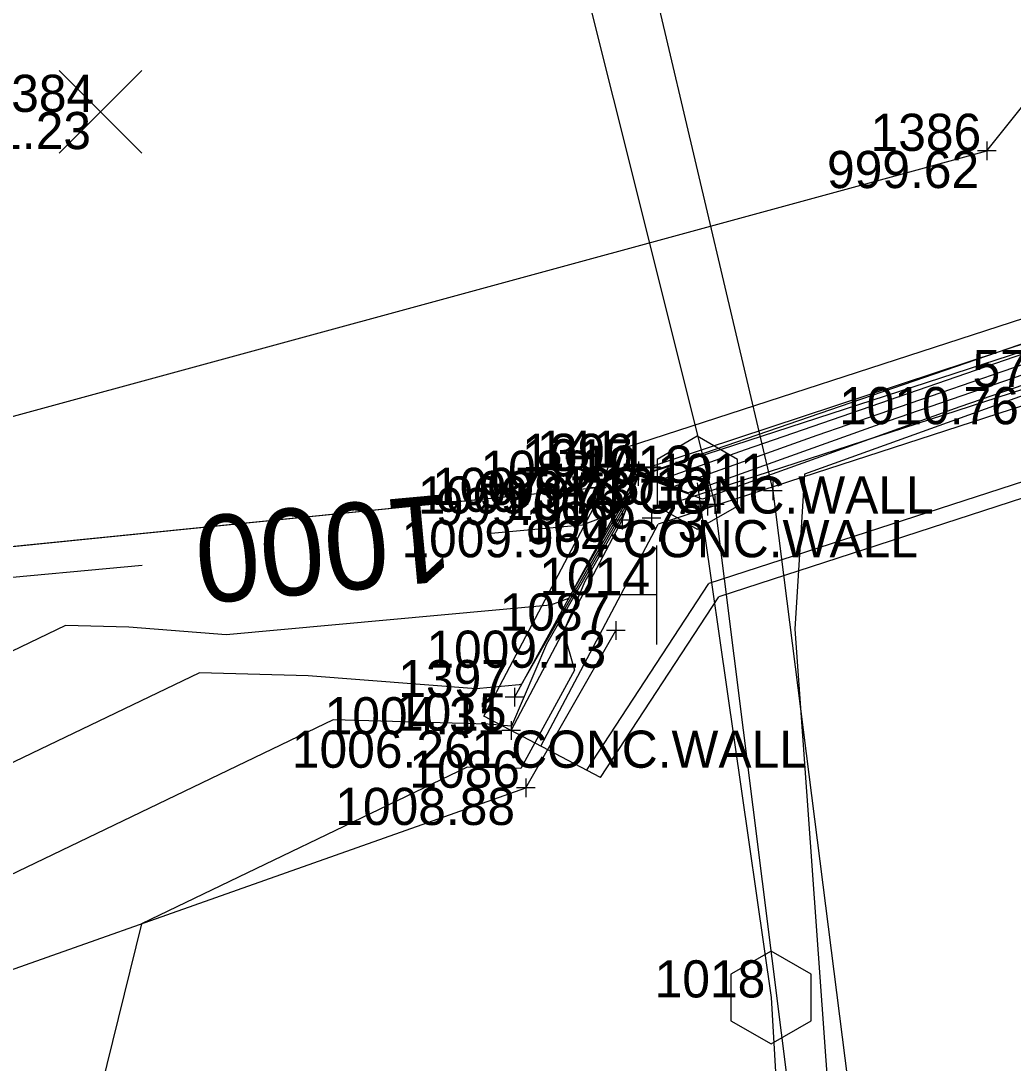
# Model space of a CAD drawing. Extents: x 2354693 to 2355622, y 637071 to 710080.
# Drawn here: x 2355324.21 to 2355356.22, y 709248.7 to 709282.34 of the extents above; entities that cross this region are included whole.
import ezdxf

# ---------------------------------------------------------------- set-up
doc = ezdxf.new("R2010")
doc.units = 0
for name, color, linetype in [('BR_X_Sub_Foot_Object', 7, 'Continuous'), ('BR_X_SV_Abut', 7, 'Continuous'), ('BR_X_SV_Beam_Seat', 7, 'Continuous'), ('DT_X_Contour_Major', 7, 'Continuous'), ('DT_X_Contour_Minor', 7, 'Continuous'), ('HY_X_Water_Edge', 7, 'Continuous'), ('PM_X_Surveyed_Line', 7, 'Continuous'), ('PV_X_EOP', 7, 'Continuous'), ('RD_X_Cells', 7, 'Continuous'), ('RD_X_GR_Rt', 7, 'Continuous'), ('SN_X_Public', 7, 'Continuous'), ('SV_X_Break_Lines', 7, 'Continuous'), ('SV_X_Random_Point', 7, 'Continuous'), ('SV_X_Shot_Marker', 7, 'Continuous'), ('SV_X_Text_Comment', 7, 'Continuous'), ('SV_X_Text_Elevation', 7, 'Continuous'), ('SV_X_Text_Name', 7, 'Continuous'), ('SV_X_Toe_of_Slope', 7, 'Continuous')]:
    doc.layers.add(name, color=color, linetype=linetype)

msp = doc.modelspace()

# ---------------------------------------------------------------- linework, layer by layer
at = {"layer": 'BR_X_Sub_Foot_Object'}
for p, q in [((2355375.767, 709278.982), (2355343.344, 709268.433)), ((2355375.36, 709273.591), (2355346.408, 709264.172)), ((2355375.359, 709273.065), (2355346.73, 709263.751)), ((2355342.905, 709257.912), (2355339.145, 709259.896))]:
    msp.add_line(p, q, dxfattribs=at)
for points in [[(2355339.145, 709259.896), (2355342.696, 709266.627), (2355343.344, 709268.433)], [(2355342.461, 709258.146), (2355346.408, 709264.172)], [(2355342.905, 709257.912), (2355346.73, 709263.751)]]:
    msp.add_lwpolyline(points, dxfattribs=at)
at = {"layer": 'BR_X_SV_Abut'}
for p, q in [((2355375.766, 709277.93), (2355344.12, 709267.634)), ((2355376.127, 709276.82), (2355344.481, 709266.525)), ((2355376.68, 709276.474), (2355344.77, 709266.093))]:
    msp.add_line(p, q, dxfattribs=at)
for points in [[(2355340.029, 709259.429), (2355343.613, 709266.223), (2355344.12, 709267.634)], [(2355340.987, 709258.924), (2355344.77, 709266.093)]]:
    msp.add_lwpolyline(points, dxfattribs=at)
at = {"layer": 'BR_X_SV_Beam_Seat'}
for p, q in [((2355344.582, 709268.212), (2355344.582, 709267.612)), ((2355344.882, 709267.912), (2355344.282, 709267.912))]:
    msp.add_line(p, q, dxfattribs=at)
at = {"layer": 'DT_X_Contour_Major'}
for points in [[(2355412.935, 709323.858), (2355412.448, 709323.101), (2355399.508, 709300.34), (2355398.693, 709299.31), (2355397.28, 709297.832), (2355380.065, 709283.245), (2355378.962, 709283.026), (2355376.473, 709281.93), (2355375.148, 709281.346), (2355373.286, 709281.525), (2355372.881, 709278.048), (2355363.645, 709274.356), (2355363.341, 709274.189), (2355362.774, 709274.062), (2355345.265, 709268.035), (2355344.363, 709267.712), (2355344.138, 709267.795), (2355344.093, 709267.669), (2355343.399, 709266.464), (2355342.314, 709266.059), (2355339.268, 709265.779)], [(2355412.935, 709323.858), (2355412.448, 709323.101), (2355399.508, 709300.34), (2355398.693, 709299.31), (2355397.28, 709297.832), (2355380.065, 709283.245), (2355378.962, 709283.026), (2355376.473, 709281.93), (2355375.148, 709281.346), (2355373.286, 709281.525), (2355372.881, 709278.048), (2355363.645, 709274.356), (2355363.341, 709274.189), (2355362.774, 709274.062), (2355345.265, 709268.035), (2355344.363, 709267.712), (2355344.138, 709267.795), (2355344.093, 709267.669), (2355343.399, 709266.464), (2355342.314, 709266.059), (2355339.268, 709265.779)], [(2355382.151, 709274.282), (2355381.711, 709274.976), (2355380.703, 709275.914), (2355376.833, 709277.662), (2355375.801, 709278.001), (2355375.775, 709278.159), (2355374.352, 709276.373), (2355372.639, 709275.689), (2355367.547, 709272.887), (2355358.064, 709270.769), (2355356.817, 709270.34), (2355349.492, 709267.71), (2355349.176, 709262.706), (2355350.806, 709240.105), (2355350.736, 709238.617), (2355350.394, 709234.495), (2355350.966, 709223.924), (2355350.775, 709220.637), (2355349.098, 709206.498), (2355348.523, 709204.444)], [(2355382.151, 709274.282), (2355381.711, 709274.976), (2355380.703, 709275.914), (2355376.833, 709277.662), (2355375.801, 709278.001), (2355375.775, 709278.159), (2355374.352, 709276.373), (2355372.639, 709275.689), (2355367.547, 709272.887), (2355358.064, 709270.769), (2355356.817, 709270.34), (2355349.492, 709267.71), (2355349.176, 709262.706), (2355350.806, 709240.105), (2355350.736, 709238.617), (2355350.394, 709234.495), (2355350.966, 709223.924), (2355350.775, 709220.637), (2355349.098, 709206.498), (2355348.523, 709204.444)], [(2355328.115, 709264.754), (2355322.767, 709264.262), (2355321.893, 709264.33), (2355321.326, 709264.346), (2355319.139, 709263.295), (2355305.5, 709255.574), (2355304.259, 709254.386), (2355286.526, 709242.434), (2355286.484, 709242.355), (2355274.307, 709214.475), (2355273.002, 709208.412), (2355271.743, 709193.195)], [(2355328.115, 709264.754), (2355322.767, 709264.262), (2355321.893, 709264.33), (2355321.326, 709264.346), (2355319.139, 709263.295), (2355305.5, 709255.574), (2355304.259, 709254.386), (2355286.526, 709242.434), (2355286.484, 709242.355), (2355274.307, 709214.475), (2355273.002, 709208.412), (2355271.743, 709193.195)]]:
    msp.add_lwpolyline(points, dxfattribs=at)
at = {"layer": 'DT_X_Contour_Minor'}
for points in [[(2355395.378, 709291.328), (2355380.244, 709278.504), (2355377.533, 709278.175), (2355377.476, 709277.579), (2355376.098, 709278.202), (2355375.927, 709278.258), (2355375.806, 709278.989), (2355375.543, 709278.66), (2355365.444, 709274.623), (2355364.182, 709273.928), (2355361.832, 709273.404), (2355347.575, 709268.496), (2355344.823, 709267.508), (2355344.134, 709267.763), (2355343.996, 709267.379), (2355341.88, 709263.698), (2355341.299, 709263.481), (2355330.832, 709262.519), (2355327.686, 709262.765), (2355325.646, 709262.822), (2355317.774, 709259.038)], [(2355395.378, 709291.328), (2355380.244, 709278.504), (2355377.533, 709278.175), (2355377.476, 709277.579), (2355376.098, 709278.202), (2355375.927, 709278.258), (2355375.806, 709278.989), (2355375.543, 709278.66), (2355365.444, 709274.623), (2355364.182, 709273.928), (2355361.832, 709273.404), (2355347.575, 709268.496), (2355344.823, 709267.508), (2355344.134, 709267.763), (2355343.996, 709267.379), (2355341.88, 709263.698), (2355341.299, 709263.481), (2355330.832, 709262.519), (2355327.686, 709262.765), (2355325.646, 709262.822), (2355317.774, 709259.038)], [(2355403.537, 709290.84), (2355391.576, 709278.322), (2355390.037, 709277.018), (2355381.334, 709275.961), (2355381.313, 709275.742), (2355376.465, 709277.932), (2355375.864, 709278.129), (2355375.79, 709278.574), (2355374.947, 709277.517), (2355369.041, 709275.156), (2355365.864, 709273.408), (2355359.948, 709272.086), (2355352.196, 709269.418), (2355345.743, 709267.101), (2355344.127, 709267.698), (2355343.804, 709266.798), (2355341.172, 709262.22), (2355340.042, 709259.574), (2355339.274, 709259.634), (2355334.287, 709259.774), (2355315.044, 709250.525)], [(2355403.537, 709290.84), (2355391.576, 709278.322), (2355390.037, 709277.018), (2355381.334, 709275.961), (2355381.313, 709275.742), (2355376.465, 709277.932), (2355375.864, 709278.129), (2355375.79, 709278.574), (2355374.947, 709277.517), (2355369.041, 709275.156), (2355365.864, 709273.408), (2355359.948, 709272.086), (2355352.196, 709269.418), (2355345.743, 709267.101), (2355344.127, 709267.698), (2355343.804, 709266.798), (2355341.172, 709262.22), (2355340.042, 709259.574), (2355339.274, 709259.634), (2355334.287, 709259.774), (2355315.044, 709250.525)], [(2355393.477, 709284.825), (2355385.14, 709277.761), (2355379.434, 709277.068), (2355379.395, 709276.661), (2355376.282, 709278.067), (2355375.896, 709278.193), (2355375.798, 709278.782), (2355375.245, 709278.088), (2355367.243, 709274.889), (2355365.023, 709273.668), (2355360.89, 709272.745), (2355349.886, 709268.957), (2355345.283, 709267.305), (2355344.131, 709267.73), (2355343.9, 709267.089), (2355340.361, 709260.932), (2355340.284, 709260.903), (2355338.897, 709260.776), (2355333.48, 709261.199), (2355329.967, 709261.298), (2355316.409, 709254.782)], [(2355393.477, 709284.825), (2355385.14, 709277.761), (2355379.434, 709277.068), (2355379.395, 709276.661), (2355376.282, 709278.067), (2355375.896, 709278.193), (2355375.798, 709278.782), (2355375.245, 709278.088), (2355367.243, 709274.889), (2355365.023, 709273.668), (2355360.89, 709272.745), (2355349.886, 709268.957), (2355345.283, 709267.305), (2355344.131, 709267.73), (2355343.9, 709267.089), (2355340.361, 709260.932), (2355340.284, 709260.903), (2355338.897, 709260.776), (2355333.48, 709261.199), (2355329.967, 709261.298), (2355316.409, 709254.782)], [(2355384.85, 709275.05), (2355383.235, 709274.854), (2355383.232, 709274.823), (2355376.649, 709277.797), (2355375.833, 709278.065), (2355375.782, 709278.367), (2355374.649, 709276.945), (2355370.84, 709275.422), (2355366.705, 709273.148), (2355359.006, 709271.428), (2355354.506, 709269.879), (2355346.203, 709266.898), (2355344.124, 709267.666), (2355343.708, 709266.508), (2355342.404, 709264.24), (2355341.712, 709262.62), (2355342.07, 709261.383), (2355340.341, 709258.201), (2355338.608, 709258.25), (2355328.095, 709253.197), (2355324.733, 709239.533), (2355325.082, 709235.631), (2355314.187, 709221.342)], [(2355384.85, 709275.05), (2355383.235, 709274.854), (2355383.232, 709274.823), (2355376.649, 709277.797), (2355375.833, 709278.065), (2355375.782, 709278.367), (2355374.649, 709276.945), (2355370.84, 709275.422), (2355366.705, 709273.148), (2355359.006, 709271.428), (2355354.506, 709269.879), (2355346.203, 709266.898), (2355344.124, 709267.666), (2355343.708, 709266.508), (2355342.404, 709264.24), (2355341.712, 709262.62), (2355342.07, 709261.383), (2355340.341, 709258.201), (2355338.608, 709258.25), (2355328.095, 709253.197), (2355324.733, 709239.533), (2355325.082, 709235.631), (2355314.187, 709221.342)]]:
    msp.add_lwpolyline(points, dxfattribs=at)
at = {"layer": 'HY_X_Water_Edge'}
for points in [[(2355338.241, 709293.806), (2355335.553, 709300.961), (2355309.837, 709289.282), (2355293.059, 709285.327), (2355275.057, 709268.764), (2355271.816, 709252.103), (2355293.45, 709267.257), (2355309.044, 709270.656), (2355323.015, 709269.316), (2355355.379, 709278.139), (2355366.295, 709291.81), (2355368.889, 709301.061)], [(2355342.789, 709267.265), (2355319.664, 709264.933)]]:
    msp.add_lwpolyline(points, dxfattribs=at)
at = {"layer": 'PM_X_Surveyed_Line'}
msp.add_lwpolyline([(2355165.86, 709547.265), (2355199.549, 709510.037), (2355233.994, 709470.593), (2355267.54, 709430.367), (2355282.605, 709410.565), (2355297.684, 709388.575), (2355309.404, 709369.446), (2355323.831, 709342.426), (2355334.056, 709318.38), (2355342.286, 709293.43), (2355348.466, 709267.168), (2355351.872, 709240.375), (2355352.964, 709217.38), (2355352.456, 709191.088), (2355350.186, 709167.624), (2355345.964, 709144.005), (2355339.847, 709117.861), (2355332.105, 709093.739), (2355322.597, 709069.077), (2355314.612, 709050.664), (2355300.362, 709021.696)], dxfattribs=at)
at = {"layer": 'PV_X_EOP'}
msp.add_lwpolyline([(2355165.324, 709546.951), (2355198.995, 709509.502), (2355233.405, 709470.111), (2355266.728, 709429.76), (2355281.934, 709410.085), (2355297.047, 709388.167), (2355308.637, 709369.042), (2355321.448, 709342.933), (2355321.339, 709342.62), (2355331.824, 709317.677), (2355340.036, 709292.971), (2355346.601, 709266.722), (2355349.963, 709239.902), (2355351.76, 709217.379), (2355351.561, 709190.756), (2355349.316, 709167.656), (2355345.615, 709144.125), (2355339.519, 709118.013), (2355331.95, 709093.674), (2355322.309, 709069.242), (2355314.268, 709051.111), (2355300.286, 709022.246)], dxfattribs=at)
at = {"layer": 'RD_X_Cells'}
for points in [[(2355344.734, 709266.677), (2355346.032, 709265.927), (2355347.33, 709266.677), (2355347.33, 709268.177), (2355346.032, 709268.927), (2355344.734, 709268.177), (2355344.734, 709266.677)], [(2355347.112, 709250.066), (2355348.411, 709249.316), (2355349.709, 709250.066), (2355349.709, 709251.566), (2355348.411, 709252.316), (2355347.112, 709251.566), (2355347.112, 709250.066)]]:
    msp.add_lwpolyline(points, dxfattribs=at)
at = {"layer": 'RD_X_GR_Rt'}
msp.add_lwpolyline([(2355346.032, 709267.427), (2355348.411, 709250.816), (2355349.36, 709234.583)], dxfattribs=at)
at = {"layer": 'SN_X_Public'}
for p, q in [((2355344.714, 709265.405), (2355344.714, 709262.205)), ((2355344.714, 709263.806), (2355343.114, 709263.806))]:
    msp.add_line(p, q, dxfattribs=at)
at = {"layer": 'SV_X_Break_Lines'}
for points in [[(2355383.541, 709274.675), (2355375.952, 709278.309), (2355344.139, 709267.811), (2355340.129, 709260.509)], [(2355288.471, 709157.099), (2355279.67, 709145.962), (2355282.08, 709180.336), (2355287.343, 709209.312), (2355300.192, 709238.194), (2355314.341, 709248.333), (2355340.498, 709257.583), (2355343.401, 709262.657)]]:
    msp.add_lwpolyline(points, dxfattribs=at)
at = {"layer": 'SV_X_Random_Point'}
for p, q in [((2355325.445, 709278.061), (2355328.111, 709280.731)), ((2355325.445, 709280.731), (2355328.111, 709278.061))]:
    msp.add_line(p, q, dxfattribs=at)
at = {"layer": 'SV_X_Shot_Marker'}
for p, q in [((2355355.679, 709278.139), (2355355.079, 709278.139)), ((2355355.379, 709278.439), (2355355.379, 709277.839)), ((2355344.139, 709268.111), (2355344.139, 709267.511)), ((2355344.542, 709268.227), (2355344.542, 709267.627)), ((2355344.439, 709267.811), (2355343.839, 709267.811)), ((2355344.12, 709267.934), (2355344.12, 709267.334)), ((2355344.12, 709267.934), (2355344.12, 709267.334)), ((2355344.842, 709267.927), (2355344.242, 709267.927)), ((2355342.789, 709267.565), (2355342.789, 709266.965)), ((2355344.42, 709267.634), (2355343.82, 709267.634)), ((2355344.42, 709267.634), (2355343.82, 709267.634)), ((2355348.466, 709267.468), (2355348.466, 709266.868)), ((2355343.089, 709267.265), (2355342.489, 709267.265)), ((2355346.601, 709267.022), (2355346.601, 709266.422)), ((2355348.766, 709267.168), (2355348.166, 709267.168)), ((2355346.901, 709266.722), (2355346.301, 709266.722)), ((2355346.357, 709266.968), (2355346.357, 709266.368)), ((2355343.613, 709266.523), (2355343.613, 709265.923)), ((2355343.613, 709266.523), (2355343.613, 709265.923)), ((2355344.555, 709266.584), (2355344.555, 709265.984)), ((2355346.657, 709266.668), (2355346.057, 709266.668)), ((2355343.913, 709266.223), (2355343.313, 709266.223)), ((2355343.913, 709266.223), (2355343.313, 709266.223)), ((2355344.855, 709266.284), (2355344.255, 709266.284)), ((2355343.701, 709262.657), (2355343.101, 709262.657)), ((2355343.401, 709262.957), (2355343.401, 709262.357)), ((2355340.129, 709260.809), (2355340.129, 709260.209)), ((2355340.429, 709260.509), (2355339.829, 709260.509)), ((2355340.029, 709259.73), (2355340.029, 709259.129)), ((2355340.029, 709259.73), (2355340.029, 709259.129)), ((2355340.329, 709259.429), (2355339.729, 709259.429)), ((2355340.329, 709259.429), (2355339.729, 709259.429)), ((2355340.498, 709257.883), (2355340.498, 709257.283)), ((2355340.798, 709257.583), (2355340.198, 709257.583))]:
    msp.add_line(p, q, dxfattribs=at)
at = {"layer": 'SV_X_Toe_of_Slope'}
for points in [[(2355338.248, 709293.892), (2355335.553, 709300.961), (2355309.837, 709289.282), (2355293.059, 709285.327), (2355275.057, 709268.764), (2355271.816, 709252.103), (2355293.45, 709267.257), (2355309.044, 709270.656), (2355323.015, 709269.316), (2355355.379, 709278.139), (2355366.295, 709291.81), (2355368.889, 709301.061)], [(2355342.789, 709267.265), (2355319.664, 709264.933), (2355304.718, 709256.214), (2355286.482, 709242.448), (2355272.744, 709215.094), (2355269.55, 709175.728), (2355269.77, 709147.806), (2355269.191, 709105.646), (2355274.675, 709084.438), (2355274.446, 709045.701), (2355249.642, 708995.534), (2355233.297, 708975.074), (2355214.476, 708950.609), (2355202.846, 708934.667), (2355185.207, 708913.176), (2355155.78, 708878.518), (2355144.347, 708868.897), (2355107.99, 708834.305)]]:
    msp.add_lwpolyline(points, dxfattribs=at)

# ---------------------------------------------------------------- texts
at = {"layer": 'BR_X_SV_Beam_Seat'}
for s, p in [('1411', (2355340.853, 709267.912)), ('1007.426', (2355337.474, 709266.712))]:
    msp.add_text(s, height=1.2, dxfattribs=at).set_placement(p)
at = {"layer": 'DT_X_Contour_Major'}
msp.add_text('1000', height=2.8, rotation=185.2511, dxfattribs=at).set_placement((2355338.008, 709267.069))
msp.add_text('1000', height=2.8, rotation=185.2511, dxfattribs=at).set_placement((2355338.008, 709267.069))
at = {"layer": 'SV_X_Text_Comment'}
for p in [(2355344.12, 709266.434), (2355343.613, 709265.023), (2355340.029, 709258.23)]:
    msp.add_text('CONC.WALL', height=1.2, dxfattribs=at).set_placement(p)
at = {"layer": 'SV_X_Text_Elevation'}
for s, p in [('1001.23', (2355320.669, 709278.196)), ('999.62', (2355350.218, 709276.939)), ('1010.767', (2355350.607, 709269.317)), ('999.03', (2355338.988, 709266.611)), ('1009.976', (2355337.012, 709266.434)), ('999.06', (2355337.597, 709266.065)), ('1009.73', (2355340.491, 709265.522)), ('1009.964', (2355336.486, 709265.023)), ('1009.13', (2355337.291, 709261.457)), ('1004.31', (2355334.007, 709259.309)), ('1006.261', (2355332.95, 709258.23)), ('1008.88', (2355334.351, 709256.383))]:
    msp.add_text(s, height=1.2, dxfattribs=at).set_placement(p)
at = {"layer": 'SV_X_Text_Name'}
for s, p in [('1384', (2355323.001, 709279.397)), ('1386', (2355351.623, 709278.139)), ('577', (2355354.916, 709270.517)), ('1396', (2355340.383, 709267.811)), ('1017', (2355340.376, 709267.634)), ('1088', (2355339.035, 709267.265)), ('1013', (2355342.316, 709267.427)), ('1011', (2355344.737, 709267.168)), ('1012', (2355342.875, 709266.722)), ('1016', (2355339.857, 709266.223)), ('1014', (2355340.937, 709263.806)), ('1087', (2355339.656, 709262.657)), ('1397', (2355336.385, 709260.509)), ('1015', (2355336.309, 709259.429)), ('1086', (2355336.741, 709257.583)), ('1018', (2355344.657, 709250.816))]:
    msp.add_text(s, height=1.2, dxfattribs=at).set_placement(p)

doc.saveas('drawing.dxf')
